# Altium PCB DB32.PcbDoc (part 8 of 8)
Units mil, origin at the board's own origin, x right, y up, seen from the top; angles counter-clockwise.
Board outline 3236.22 x 4456.69 mil, 8 copper layers (Top Layer, MidLayer1, MidLayer2, GND-Layer5, MidLayer3, VCC, MidLayer4, Bottom Layer), stack 61.8 mil thick; 207 components, 474 nets, 1777 pads, 1474 vias.
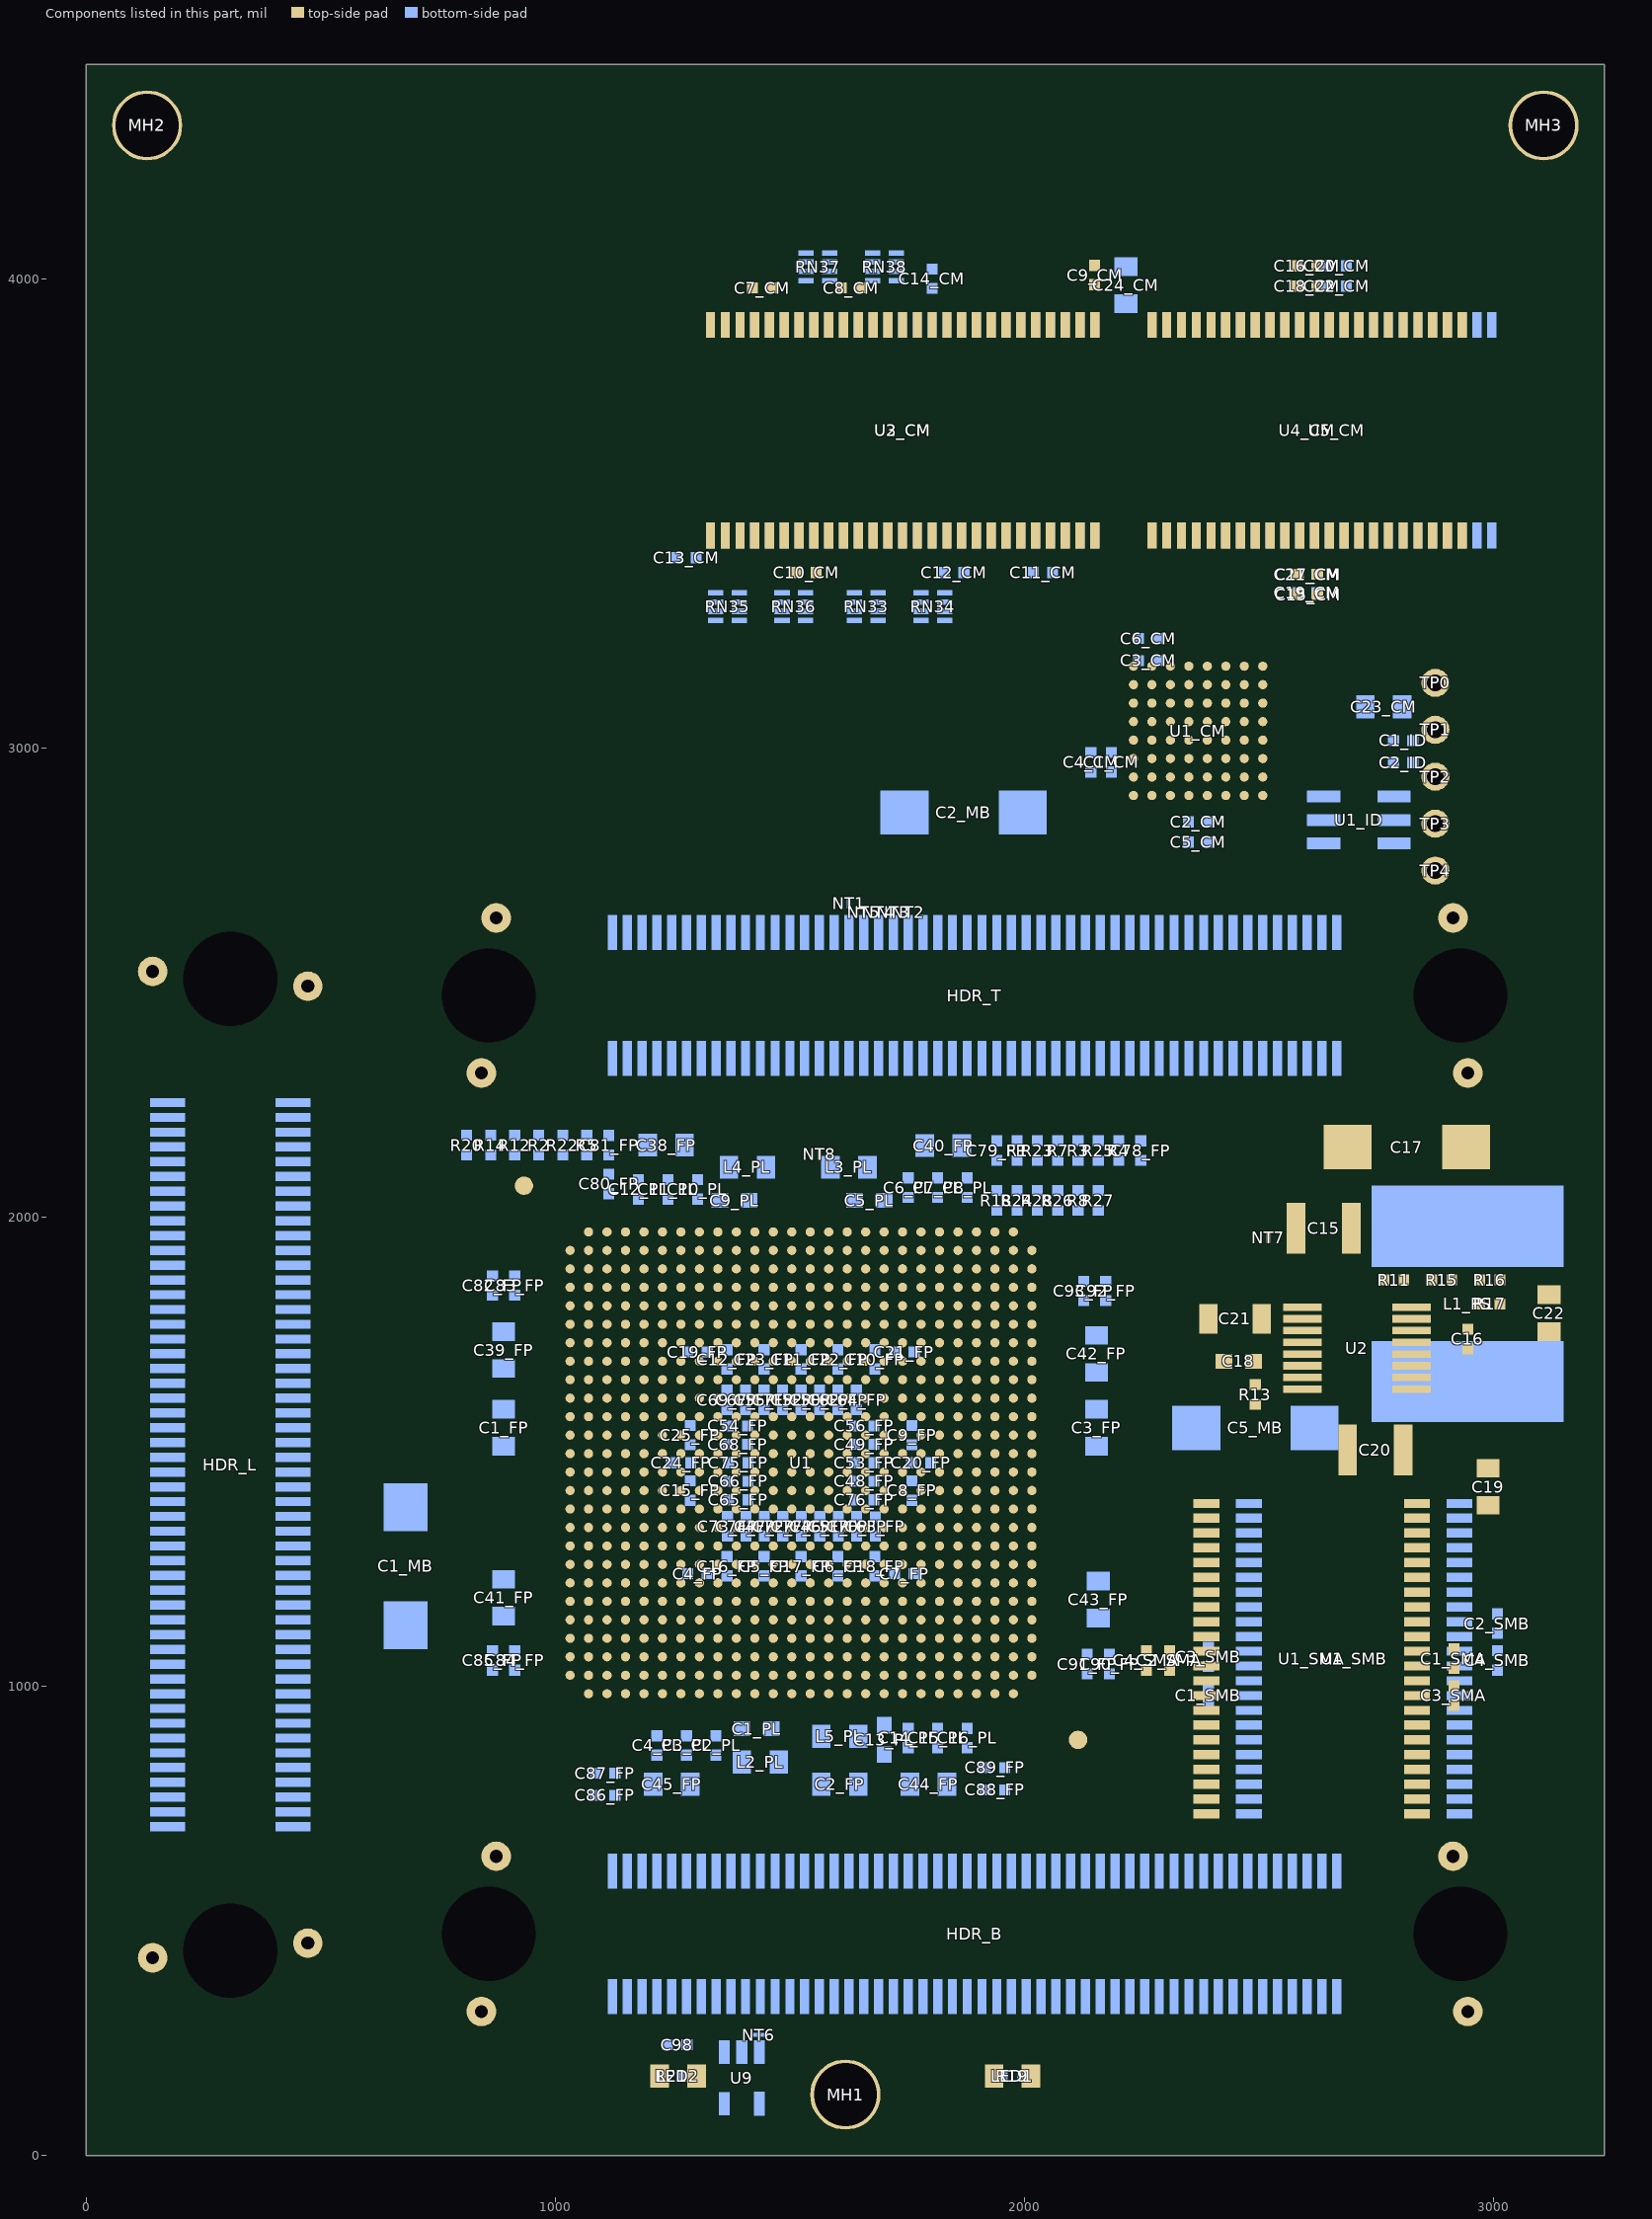
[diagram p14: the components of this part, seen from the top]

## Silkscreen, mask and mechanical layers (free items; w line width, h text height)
Top Overlay:
  region: 1073.79,617.74 998.77,617.74 998.77,318.48 1073.79,318.48
  rectangle: 2715.79,318.48 2788.79,617.48
  rectangle: 998.77,318.48 1627.79,354.48
  rectangle: 998.77,581.74 1627.79,617.74
  region: 146.51,4136.09 139.44,4129.02 164.19,4104.27 171.26,4111.34
  rectangle: 136.51,4026.09 146.51,4136.09
  region: 88.59,4111.34 95.66,4104.27 120.41,4129.02 113.34,4136.09
  region: 123.34,4136.09 113.34,4136.09 113.34,4026.09 123.34,4026.09
  region: 3122.89,4136.09 3115.82,4129.02 3140.56,4104.27 3147.64,4111.34
  rectangle: 3112.89,4026.09 3122.89,4136.09
  region: 3064.97,4111.34 3072.04,4104.27 3096.79,4129.02 3089.71,4136.09
  region: 3099.71,4136.09 3089.71,4136.09 3089.71,4026.09 3099.71,4026.09
  region: 1814.46,159.54 1814.46,169.54 1779.46,169.54 1779.46,159.54
  region: 1772.38,166.61 1779.46,159.54 1857.24,237.33 1850.17,244.4
  rectangle: 1756,183 1766,218
  region: 1840.85,253.71 1833.78,260.78 1756,183 1763.07,175.93
  rectangle: 2588.92,4308.12 2736.13,4350.06
  rectangle: 2736.22,1620.75 2768.58,1820.75
  region: 1818.9,4447.83 1693.9,4447.83 1693.9,4181.1 1818.9,4181.1
  rectangle: 2858.27,4204.72 2980.31,4318.9
  region: 1699.8,4344.49 1699.8,4199.8 1822.83,4199.8 1822.83,4344.49
  rectangle: 2980.31,4181.1 3232.28,4200.79
  rectangle: 2917.32,4181.1 2980.31,4456.69
  region: 2968.5,4438.98 2968.5,4456.69 1693.9,4456.69 1693.9,4438.98
  region: 2984.25,4181.1 2984.25,4213.58 1693.9,4213.58 1693.9,4181.1
  region: 1689.96,4181.1 1689.96,4456.69 1670.28,4456.69 1670.28,4181.1
  region: 1598.43,4181.1 1598.43,4456.69 1593.51,4456.69 1593.51,4181.1
  region: 1618.11,4181.1 1618.11,4456.69 1610.24,4456.69 1610.24,4181.1
  region: 1640.75,4181.1 1640.75,4456.69 1628.94,4456.69 1628.94,4181.1
  region: 1664.37,4181.1 1664.37,4456.69 1649.61,4456.69 1649.61,4181.1
  region: 1579.72,4181.1 1579.72,4456.69 1576.77,4456.69 1576.77,4181.1
  rectangle: 2877.95,4204.72 2980.31,4318.9
  region: 1987.22,4447.83 1700.79,4447.83 1700.79,4314.96 1987.22,4314.96
  rectangle: 2696.77,4307.09 2980.31,4456.69
  rectangle: 2238.19,3502.95 2966.89,3595.47
  rectangle: 1301.18,3503.94 2179.13,3596.46
  rectangle: 2049.67,129.92 2063.98,208.66
  rectangle: 1337.26,129.92 1351.38,208.66
  region: 2787.4,695.23 2787.4,1424.21 2694.88,1424.21 2694.88,695.23
  lines w3: 1118.09,192.91 1133.09,202.91 1123.09,202.91 1143.09,217.91 ; 1133.09,207.91 1143.09,217.91 ; 1133.09,212.91 1143.09,217.91 ; 2137.52,187.01 2152.52,197.01 2142.52,197.01 2162.52,212.01 ; 2152.52,202.01 2162.52,212.01 ; 2152.52,207.01 2162.52,212.01
  lines w5: 971.79,2028.21 992.13,2007.87 ; 1078.13,171.78 1103.06,171.78 ; 1103.06,173.36 1126.68,173.36 ; 1104.64,163.12 1126.68,172.05 ; 1104.64,180.97 1126.68,172.05 ; 1105.03,168.63 1126.68,172.96 ; 1105.03,175.46 1126.68,171.13 ; 1126.68,156.3 1126.68,187.79 ; 1126.68,171.78 1150.04,171.78 ; 1329.1,3386.03 1329.1,3414.79 ; 2097.56,165.88 2122.48,165.88 ; 2122.48,167.45 2146.1,167.45 ; 2124.06,157.21 2146.1,166.14 ; 2124.06,175.07 2146.1,166.14 ; 2124.45,162.73 2146.1,167.06 ; 2124.45,169.56 2146.1,165.23 ; 2146.1,150.39 2146.1,181.89 ; 2146.1,165.88 2169.46,165.88 ; 2260.08,1094.39 2280.3,1122.24 ; 2271.78,3384.98 2271.78,3413.74 ; 2288.68,987.98 2308.9,1015.83 ; 2646.32,3273.29 2625.98,3252.95 ; 2907.18,728.42 2878.41,728.42 ; 2908.93,1634.16 2880.16,1634.16 ; 992.13,2007.87 964.13,2020.87 971.68,2028.32 979.13,2035.87 992.13,2007.87 ; 1126.68,172.05 1103.06,156.3 1103.06,187.79 1126.68,172.05 ; 1329.1,3414.79 1318.5,3385.8 1329.1,3385.88 1339.71,3385.8 1329.1,3414.79 ; 2146.1,166.14 2122.48,181.89 2122.48,150.39 2146.1,166.14 ; 2271.78,3413.74 2282.39,3384.75 2271.78,3384.83 2261.17,3384.75 2271.78,3413.74 ; 2625.98,3252.95 2638.98,3280.95 2646.43,3273.4 2653.98,3265.95 2625.98,3252.95 ; 2878.41,728.42 2907.4,717.82 2907.33,728.42 2907.4,739.03 2878.41,728.42 ; 2880.16,1634.16 2909.15,1623.56 2909.08,1634.16 2909.15,1644.77 2880.16,1634.16
  lines w7: 971.13,2022.87 978.12,2015.87 ; 977.13,2028.87 984.13,2021.87 ; 1324.86,3389.33 1324.86,3399.23 ; 1333.35,3389.33 1333.35,3399.23 ; 2267.54,3388.29 2267.54,3398.18 ; 2276.02,3388.29 2276.02,3398.18 ; 2633.98,3266.95 2640.98,3273.95 ; 2639.98,3260.95 2646.98,3267.95 ; 2893.97,724.18 2903.87,724.18 ; 2893.97,732.67 2903.87,732.67 ; 2895.72,1629.92 2905.62,1629.92 ; 2895.72,1638.41 2905.62,1638.41
  lines w7.87: 1301.18,3722.33 ccw(c1301.18,3752.07) 1301.18,3781.82 ; 2179.13,3722.33 cw(c2179.13,3752.07) 2179.13,3781.82 ; 3232.28,4185.04 3232.28,4200.79 ; 3232.28,4200.79 2980.31,4200.79 2980.31,4452.76 3232.28,4452.76 3232.28,4200.79
  text "LatticeECP™" at 2001.19,4336.36 h125.98
  text "LFECP33E-3FN672C" at 1838.58,4216.54 h118.11
  text "SRAM-256Kx16" at 2352.07,3683.79 h50
  text "DRAM-16Mx16" at 1482.53,3682.61 h50
  text "FLASH" at 2491.1,2767.2 h34
  text "1831" at 2721.4,1671.7 h40 r90
  text "SRAM-256Kx16" at 2605.68,808.76 h50 r90
  text "DB32.08" at 1027.8,488.46 h98.43
  text "LFECP33E-3FN672C" at 1027.8,430.47 h60
  text "Lattice Daughter Board" at 1028.31,354.49 h60
  text "DB32.08" at 1625.79,318.46 h60
  text "PROGRAM" at 1145,60 h55.12
  text "POWER" at 1895,60 h55.12
Bottom Overlay:
  drawing of 1294 lines, arcs and shapes, not listed
  text "LatticeECP™" at 2690.91,4336.53 h125.98
  text "LFECP33E-3FN672C" at 2853.52,4216.71 h118.11
  text "MANUFACTURE" at 1006.78,3830.86 h40
  text "DATE" at 1007.88,3764.06 h40
  text "SRAM-256Kx16" at 2939.9,3684 h50
  text "DRAM-16Mx16" at 1997.78,3682.61 h50
  text "COMPLIANCE:" at 1182.36,3081.45 h45
  text "CLASS 2" at 432.36,2991.45 h40
  text "IPC-A-600H" at 1092.36,2991.45 h40
  text "CLASS 2" at 432.36,2911.45 h40
  text "TYPE 3" at 682.36,2911.45 h40
  text "IPC-6012D" at 1092.36,2911.45 h40
  text "DS2406" at 2711.2,2774.8 h28 r270
  text "1" at 116.93,2272.44 h40
  text "1" at 1089.9,2258.51 h40
  text "SRAM-256Kx16" at 2709.68,784.5 h50 r270
  text "1" at 1070.87,255.91 h40
  text "DB32" at 412.16,123.67 h120
Bottom Solder:
  region: 2455.79,1920.32 2455.79,2040.32 2305.79,2040.32 2305.79,1920.32
PCB Boundary:
  lines w3.94: 1523.62,4456.69 3236.22,4456.69 ; 1523.62,4456.69 3236.22,4456.69 ; 1523.62,4456.69 0,4456.69 0,0 1618.11,0 3236.22,0 3236.22,4456.69 ; 1523.62,4456.69 3236.22,4456.69 ; 1523.62,4456.69 3236.22,4456.69
Mechanical 7:
  lines w7.87: 2437.52,1720.19 2260.94,1847.52 2260.94,2044.37 2437.52,2171.7 ; 2495.47,1746.69 2318.9,1874.02 2318.9,2070.87 2495.47,2198.19 ; 2587.72,1945.94 2666.46,1945.94 ; 2627.09,1906.57 2627.09,1985.32 ; 2645.67,1972.44 2724.41,1972.44 ; 2685.04,1933.07 2685.04,2011.81 ; 2820.59,1720.19 2997.17,1847.52 2997.17,2044.37 2820.59,2171.7 ; 2878.54,1746.69 3055.12,1874.02 3055.12,2070.87 2878.54,2198.19
Keep Away From Edge:
  lines w7.87: 200,200 200,4250 3030,4250 3030,200 200,200

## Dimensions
2865.92,4456.69 to 3106.3,4326.77 on Dimensions
2929.14,472.44 to 3244.09,0 on Dimensions
1618.11,129.92 to 3244.09,0 on Dimensions
307.09,437.01 to -19.69,0 on Dimensions
1618.11,153.54 to 3236.22,19.69 on Dimensions
2929.14,472.44 to 3236.22,-3.94 on Dimensions
0,4456.69 to -19.69,0 on Dimensions
3236.22,0 to 0,4059.06 on Dimensions
307.09,-15.75 to 0,4275.59 on Dimensions
129.92,4342.52 to 0,15.75 on Dimensions
3106.3,4326.77 to 3236.22,0 on Dimensions
2929.13,472.44 to 2929.13,2472.44 on Dimensions
307.09,437.01 to 858.27,472.44 on Dimensions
